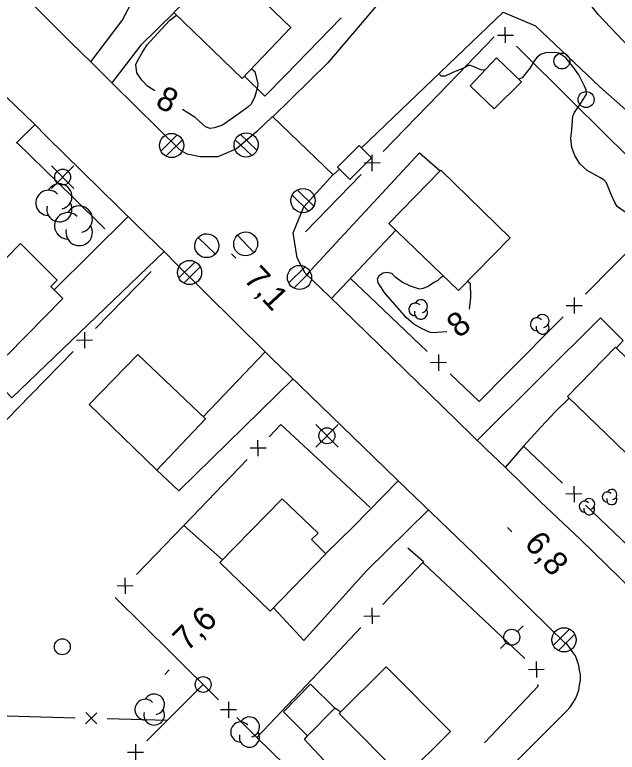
# Model space of a CAD drawing. Extents: x 381879 to 384696, y 5564785 to 5567594.
# Drawn here: x 383164.9 to 383240.4, y 5565288.9 to 5565381.4 of the extents above; entities that cross this region are included whole.
import ezdxf

# ---------------------------------------------------------------- set-up
doc = ezdxf.new("R2010")
doc.units = 0
for name, color, linetype in [('Niveau 19', 7, 'Continuous'), ('Niveau 2', 7, 'Continuous'), ('Niveau 21', 7, 'Continuous'), ('Niveau 3', 7, 'Continuous'), ('Niveau 31', 7, 'Continuous'), ('Niveau 36', 7, 'Continuous'), ('Niveau 37', 7, 'Continuous'), ('Niveau 44', 7, 'Continuous')]:
    doc.layers.add(name, color=color, linetype=linetype)

msp = doc.modelspace()

# ---------------------------------------------------------------- linework, layer by layer
at = {"layer": 'Niveau 19'}
for points in [[(383174.4, 5565375.49), (383178.35, 5565380.67), (383181.39, 5565386.48), (383186.67, 5565392.25), (383190.82, 5565387.81)], [(383184.84, 5565381.67), (383180.62, 5565377.54), (383177.05, 5565372.85)], [(383165.13, 5565365.37), (383167.39, 5565367.61)], [(383201.48, 5565348.82), (383215.62, 5565364.08), (383218.22, 5565361.81)], [(383179.07, 5565356.11), (383169.82, 5565346.88)], [(383212.64, 5565354.39), (383204.57, 5565345.83)], [(383163.77, 5565338.83), (383161.59, 5565336.42), (383164.5, 5565333.35), (383183.6, 5565351.69)], [(383240.3, 5565339.6), (383241.18, 5565340.54), (383238.33, 5565343.4), (383222.87, 5565328)], [(383196.27, 5565339.13), (383188.51, 5565330.97)], [(383182.7, 5565324.3), (383185.44, 5565321.7), (383199.77, 5565335.74)], [(383232.63, 5565331.58), (383234.39, 5565333.32)], [(383228.67, 5565327.31), (383226.37, 5565324.63)], [(383203.86, 5565313.84), (383207.34, 5565317.2), (383212.96, 5565322.94)], [(383216.77, 5565319.3), (383208.96, 5565311.64), (383201.14, 5565302.91), (383197.3, 5565307.01)], [(383205.75, 5565293.94), (383205.01, 5565294.41)], [(383215.47, 5565275.27), (383201.2, 5565290.52), (383201.6, 5565290.97)]]:
    msp.add_lwpolyline(points, dxfattribs=at)
at = {"layer": 'Niveau 2'}
for points in [[(383182.45, 5565371.87), (383181.53, 5565372.43), (383180.79, 5565373.18), (383180.19, 5565374.12), (383180.06, 5565375.16), (383180.28, 5565375.64), (383180.87, 5565376.71), (383181.48, 5565377.62), (383182.3, 5565378.56), (383184.27, 5565380.68), (383185.16, 5565381.36)], [(383242.14, 5565356.12), (383240.41, 5565357.36), (383240.12, 5565357.84), (383239.67, 5565358.87), (383239.1, 5565360.31), (383238.74, 5565360.69), (383238.25, 5565360.98), (383236.64, 5565361.88), (383235.74, 5565362.69), (383235.09, 5565363.73), (383234.72, 5565364.77), (383234.62, 5565365.87), (383234.73, 5565366.98), (383234.84, 5565368.67), (383235.07, 5565369.13), (383235.94, 5565370.44), (383236.56, 5565371.42), (383236.51, 5565371.97), (383236.33, 5565372.46), (383235.63, 5565373.86), (383235, 5565374.76), (383233.96, 5565376.01), (383233.12, 5565376.57), (383232.57, 5565376.66), (383231.45, 5565376.62), (383230.88, 5565376.45), (383230.4, 5565376.09), (383230.06, 5565375.65)], [(383230.06, 5565375.65), (383229.5, 5565374.74), (383228.5, 5565373.49), (383228.07, 5565373.32)], [(383194.57, 5565374.63), (383194.97, 5565374.28)], [(383223.82, 5565374.43), (383223.32, 5565374.49), (383222.36, 5565374.91), (383221.87, 5565375.06), (383221.22, 5565374.75), (383219.82, 5565374.17), (383218.86, 5565373.68), (383218.32, 5565373.68), (383218.12, 5565374.05)], [(383194.97, 5565374.28), (383195.34, 5565372.68), (383195.26, 5565372.18), (383194.97, 5565371.16), (383194.51, 5565370.17), (383194.09, 5565369.81), (383192.72, 5565368.79), (383190.9, 5565367.56), (383189.9, 5565367.2), (383189.38, 5565367.15), (383188.8, 5565367.34), (383188.31, 5565367.75), (383187.51, 5565368.53), (383185.91, 5565369.5)], [(383219.06, 5565341.64), (383217.21, 5565341.5), (383216.97, 5565341.53), (383215.95, 5565342), (383214.91, 5565342.59), (383213.94, 5565343.44), (383213.17, 5565344.34), (383211.33, 5565346.44), (383210.45, 5565347.76), (383210.38, 5565348.27), (383210.63, 5565348.74), (383211.07, 5565349.02), (383211.57, 5565349.12), (383212.12, 5565348.98), (383212.54, 5565348.58), (383213.48, 5565347.88), (383214.46, 5565347.4), (383215.59, 5565347.03), (383216.13, 5565347.12), (383216.61, 5565347.3), (383217.48, 5565347.87), (383217.95, 5565348.1), (383218.36, 5565348.49), (383218.59, 5565348.64)], [(383221.68, 5565348), (383221.99, 5565347.72)], [(383221.99, 5565347.72), (383222.04, 5565345.95), (383221.84, 5565344.46)]]:
    msp.add_lwpolyline(points, dxfattribs=at)
at = {"layer": 'Niveau 21'}
for points in [[(383238.06, 5565416.31), (383235.15, 5565406.99), (383223.7, 5565395.12), (383210.55, 5565382.93), (383204.15, 5565375.38), (383197.24, 5565368.6)], [(383287.03, 5565366.47), (383272.7, 5565366.43), (383260.45, 5565365.37), (383253.79, 5565365.29), (383248.29, 5565370.63), (383238.04, 5565381.44), (383233.93, 5565386.75), (383234.49, 5565390.02), (383241.22, 5565399.26), (383243.8, 5565407.14), (383243.07, 5565412.42), (383243.64, 5565416.32)], [(383160.7, 5565389.1), (383171.8, 5565378)], [(383208.37, 5565364.72), (383226.14, 5565381.73), (383230.19, 5565380.03), (383238.26, 5565372.36), (383249.41, 5565362.48), (383256.66, 5565360.44), (383266.73, 5565360.61), (383280.92, 5565361.12), (383288.21, 5565361.47)], [(383171.8, 5565378), (383174.6, 5565375.3)], [(383174.6, 5565375.3), (383177.2, 5565372.7)], [(383177.2, 5565372.7), (383185.6, 5565364.4)], [(383167.3, 5565367.7), (383163.8, 5565371.1)], [(383197.21, 5565368.63), (383195.18, 5565366.73), (383192.68, 5565364.58), (383190.34, 5565363.58), (383188.1, 5565363.58), (383186.49, 5565363.91), (383185.6, 5565364.4)], [(383197.21, 5565368.63), (383204.82, 5565361.32)], [(383180.1, 5565355.1), (383168.9, 5565366.1), (383167.3, 5565367.7)], [(383201.3, 5565349), (383200.3, 5565350.9), (383199.8, 5565354.03), (383201.12, 5565357.3), (383204.79, 5565361.35)], [(383204.82, 5565361.32), (383205.59, 5565362.05)], [(383183.8, 5565351.5), (383180.1, 5565355.1)], [(383196.4, 5565339), (383185, 5565350.3), (383183.8, 5565351.5)], [(383201.3, 5565349), (383204.3, 5565346.1)], [(383204.3, 5565346.1), (383218.6, 5565332.2), (383224, 5565326.9)], [(383199.3, 5565336.2), (383197.1, 5565338.3), (383196.4, 5565339)], [(383212.9, 5565323), (383209.9, 5565325.9), (383199.3, 5565336.2)], [(383224, 5565326.9), (383225.5, 5565325.5), (383226.4, 5565324.6)], [(383226.4, 5565324.6), (383230.8, 5565320.3)], [(383234, 5565302.5), (383222.5, 5565313.8), (383212.9, 5565323)], [(383242.4, 5565309.2), (383235.8, 5565315.6), (383230.8, 5565320.3)], [(383234.1, 5565294.1), (383234.5, 5565294.5), (383234.8, 5565295), (383235.2, 5565295.6), (383235.4, 5565296.1), (383235.6, 5565296.7), (383235.7, 5565297.3), (383235.8, 5565298), (383235.8, 5565298.6), (383235.7, 5565299.2), (383235.6, 5565299.8), (383235.4, 5565300.4), (383235.2, 5565301), (383234.8, 5565301.5), (383234.5, 5565302), (383234.1, 5565302.5), (383234, 5565302.5)], [(383219.3, 5565279.2), (383221.3, 5565281.3), (383234.1, 5565294.1)]]:
    msp.add_lwpolyline(points, dxfattribs=at)
at = {"layer": 'Niveau 3'}
for p, q in [((383192.04, 5565351.42), (383192.61, 5565350.85)), ((383226.65, 5565317.08), (383227.22, 5565316.53)), ((383183.68, 5565298.67), (383184.25, 5565299.24))]:
    msp.add_line(p, q, dxfattribs=at)
at = {"layer": 'Niveau 31'}
for points in [[(383193.4, 5565373.4), (383199.5, 5565379.8), (383191, 5565388), (383184.8, 5565381.7)], [(383228.4, 5565373), (383225.3, 5565376), (383222, 5565372.5), (383225, 5565369.6)], [(383209.62, 5565363.46), (383206.88, 5565360.75), (383205.34, 5565362.3), (383208.08, 5565365.01)], [(383220.5, 5565346.8), (383227, 5565353.4), (383218.3, 5565361.9), (383211.8, 5565355.2)], [(383163.9, 5565338.7), (383170.9, 5565345.8), (383169.4, 5565347.3), (383170.2, 5565348.1), (383165.6, 5565352.7), (383157.8, 5565344.8)], [(383234.2, 5565333.5), (383240.2, 5565339.7), (383248.8, 5565331.4), (383242.8, 5565325.2)], [(383182.7, 5565324.3), (383188.8, 5565330.7), (383180.3, 5565338.8), (383174.2, 5565332.5)], [(383198.4, 5565320.7), (383202.9, 5565316.4), (383202.1, 5565315.6), (383203.9, 5565313.8), (383196.9, 5565306.6), (383190.6, 5565312.7)], [(383211.46, 5565299.61), (383219.5, 5565291.51), (383213.61, 5565285.67), (383205.57, 5565293.77)], [(383205.01, 5565294.41), (383201.6, 5565290.97), (383198.56, 5565293.98), (383201.97, 5565297.42)]]:
    msp.add_lwpolyline(points, close=True, dxfattribs=at)
at = {"layer": 'Niveau 36'}
for p, q in [((383185.23, 5565366.34), (383183.17, 5565364.3)), ((383195.24, 5565364.43), (383193.14, 5565366.42)), ((383183.83, 5565363.66), (383185.89, 5565365.7)), ((383192.52, 5565365.73), (383194.62, 5565363.74)), ((383172.29, 5565362.44), (383169.47, 5565359.62)), ((383172.29, 5565359.62), (383169.47, 5565362.44)), ((383199.66, 5565358.76), (383201.73, 5565356.73)), ((383202.36, 5565357.4), (383200.29, 5565359.43)), ((383190.03, 5565351.39), (383187.87, 5565353.47)), ((383194.87, 5565351.58), (383192.79, 5565353.74)), ((383187.48, 5565350.41), (383185.42, 5565348.37)), ((383186.08, 5565347.73), (383188.14, 5565349.77)), ((383201.27, 5565349.79), (383199.21, 5565347.75)), ((383199.87, 5565347.11), (383201.93, 5565349.15)), ((383205.43, 5565330), (383202.61, 5565327.18)), ((383205.43, 5565327.18), (383202.61, 5565330)), ((383228.62, 5565304.74), (383227.91, 5565304.04)), ((383234.44, 5565304.34), (383232.38, 5565302.3)), ((383233.04, 5565301.66), (383235.1, 5565303.7)), ((383225.8, 5565301.91), (383226.49, 5565302.63))]:
    msp.add_line(p, q, dxfattribs=at)
for centre, radius in [((383233.493, 5565375.6), 1), ((383236.523, 5565370.76), 1), ((383184.538, 5565365.002), 1.518), ((383170.872, 5565361.035), 1), ((383186.788, 5565349.072), 1.518), ((383200.578, 5565348.452), 1.518), ((383204.012, 5565328.595), 1), ((383227.197, 5565303.325), 1), ((383233.748, 5565303.002), 1.518), ((383170.833, 5565302.13), 1), ((383188.493, 5565297.4), 1)]:
    msp.add_circle(centre, radius, dxfattribs=at)
for centre, major_axis, ratio in [((383193.882, 5565365.072), (0.024, 1.517), 0.999984), ((383201.008, 5565358.088), (-0.017, -1.517), 0.999984), ((383188.942, 5565352.434), (0.016, 1.5), 0.999983), ((383193.823, 5565352.665), (0.015, 1.5), 0.999983)]:
    msp.add_ellipse(centre, major_axis=major_axis, ratio=ratio, dxfattribs=at)
at = {"layer": 'Niveau 37'}
for p, q in [((383226.4, 5565377.86), (383226.39, 5565379.86)), ((383225.39, 5565378.86), (383227.4, 5565378.86)), ((383209.71, 5565361.8), (383209.68, 5565363.81)), ((383210.7, 5565362.82), (383208.69, 5565362.79)), ((383235.04, 5565345.94), (383235.04, 5565343.94)), ((383234.04, 5565344.94), (383236.04, 5565344.95)), ((383173.6, 5565341.6), (383173.62, 5565339.6)), ((383172.61, 5565340.59), (383174.61, 5565340.61)), ((383217.99, 5565338.77), (383218.03, 5565336.76)), ((383219.01, 5565337.79), (383217.01, 5565337.74)), ((383195.4, 5565326.04), (383195.37, 5565328.04)), ((383196.39, 5565327.06), (383194.38, 5565327.02)), ((383234.98, 5565322.28), (383235.03, 5565320.28)), ((383236, 5565321.3), (383234, 5565321.25)), ((383178.75, 5565308.75), (383178.71, 5565310.76)), ((383179.73, 5565309.77), (383177.73, 5565309.74)), ((383209.64, 5565307), (383209.69, 5565305)), ((383208.66, 5565305.97), (383210.67, 5565306.02)), ((383230.25, 5565300.27), (383230.31, 5565298.26)), ((383231.28, 5565299.29), (383229.28, 5565299.24)), ((383191.68, 5565295.22), (383191.69, 5565293.22)), ((383173.73, 5565292.48), (383175.18, 5565293.86)), ((383175.14, 5565292.45), (383173.77, 5565293.9)), ((383192.68, 5565294.23), (383190.68, 5565294.21)), ((383180, 5565289.92), (383180, 5565287.92)), ((383179, 5565288.92), (383181, 5565288.92))]:
    msp.add_line(p, q, dxfattribs=at)
for points in [[(383205.79, 5565381.01), (383198.81, 5565373.84)], [(383218.04, 5565371.43), (383224.99, 5565378.61)], [(383227.81, 5565377.45), (383234.91, 5565370.41)], [(383198.81, 5565373.84), (383196.22, 5565371.17), (383193.7, 5565373.71)], [(383211.08, 5565364.24), (383218.04, 5565371.43)], [(383234.91, 5565370.41), (383242.01, 5565363.36)], [(383165.05, 5565365.28), (383165.13, 5565365.37), (383172.19, 5565358.46)], [(383201.35, 5565354.18), (383208.3, 5565361.37)], [(383172.19, 5565358.46), (383176.16, 5565354.57)], [(383243.49, 5565353.46), (383236.45, 5565346.36)], [(383181.99, 5565349.19), (383175.01, 5565342.03)], [(383209.34, 5565346.06), (383206.94, 5565348.35)], [(383216.57, 5565339.15), (383209.34, 5565346.06)], [(383233.63, 5565343.52), (383226.59, 5565336.42)], [(383172.21, 5565339.17), (383165.23, 5565332.01)], [(383226.59, 5565336.42), (383223.1, 5565332.9), (383219.46, 5565336.38)], [(383165.23, 5565332.01), (383159.79, 5565326.43), (383158.2, 5565327.96)], [(383230.88, 5565329.7), (383232.63, 5565331.58)], [(383196.77, 5565328.48), (383198.25, 5565330.01), (383204.01, 5565324.65)], [(383233.55, 5565322.66), (383228.67, 5565327.31), (383230.88, 5565329.7)], [(383187.06, 5565318.4), (383194, 5565325.6)], [(383204.01, 5565324.65), (383209.44, 5565319.59)], [(383243.69, 5565313), (383236.45, 5565319.9)], [(383180.12, 5565311.2), (383186.06, 5565317.36), (383187.06, 5565318.4)], [(383186.06, 5565317.36), (383190.92, 5565313.02)], [(383214.18, 5565314.54), (383216.13, 5565312.82), (383216.03, 5565312.72), (383211.04, 5565307.45)], [(383221.55, 5565307.5), (383216.23, 5565312.53), (383216.23, 5565312.54), (383216.03, 5565312.72)], [(383184.55, 5565301.29), (383177.44, 5565308.32)], [(383228.82, 5565300.64), (383221.55, 5565307.5)], [(383208.29, 5565304.54), (383201.41, 5565297.28)], [(383190.43, 5565295.49), (383184.55, 5565301.29)], [(383188.48, 5565297.41), (383181.41, 5565290.34)], [(383201.41, 5565297.28), (383195.23, 5565290.75), (383192.73, 5565293.25)], [(383223.77, 5565290.09), (383230.52, 5565297.2), (383230.53, 5565297.4)], [(383162.46, 5565293.5), (383172.46, 5565293.23)], [(383176.46, 5565293.12), (383183.98, 5565292.91)], [(383195.23, 5565290.75), (383202.37, 5565283.75)]]:
    msp.add_lwpolyline(points, dxfattribs=at)
at = {"layer": 'Niveau 44'}
for centre, radius, start, end in [((383170.459, 5565358.6), 1.586, 282.26915, 149.72624), ((383169.095, 5565357.807), 1.586, 44.11535, 269.80394), ((383170.459, 5565357.014), 1.586, 166.93684, 29.62121), ((383172.946, 5565355.76), 1.66, 282.26915, 149.72624), ((383171.519, 5565354.93), 1.66, 44.11535, 269.80394), ((383172.946, 5565354.1), 1.66, 166.93684, 29.62121), ((383215.81, 5565344.842), 0.815, 282.26915, 149.72624), ((383215.109, 5565344.434), 0.815, 44.11535, 269.80394), ((383215.81, 5565344.027), 0.815, 166.93684, 29.62121), ((383231.061, 5565342.985), 0.821, 282.26915, 149.72624), ((383230.355, 5565342.575), 0.821, 44.11535, 269.80394), ((383231.061, 5565342.164), 0.821, 166.93684, 29.62121), ((383239.739, 5565321.227), 0.64, 282.26915, 149.72624), ((383236.918, 5565320.049), 0.681, 282.26915, 149.72624), ((383239.188, 5565320.907), 0.64, 44.11535, 269.80394), ((383239.739, 5565320.587), 0.64, 166.93684, 29.62121), ((383236.333, 5565319.709), 0.681, 44.11535, 269.80394), ((383236.918, 5565319.368), 0.681, 166.93684, 29.62121), ((383182.342, 5565294.903), 1.298, 282.26915, 149.72624), ((383181.226, 5565294.255), 1.298, 44.11535, 269.80394), ((383182.342, 5565293.606), 1.298, 166.93684, 29.62121), ((383194.294, 5565292.065), 1.264, 282.26915, 149.72624), ((383193.207, 5565291.433), 1.264, 44.11535, 269.80394), ((383194.294, 5565290.801), 1.264, 166.93684, 29.62121)]:
    msp.add_arc(centre, radius, start, end, dxfattribs=at)

# ---------------------------------------------------------------- texts
at = {"layer": 'Niveau 2'}
for rotation, p in [(332.17861, (383182.34, 5565369.99)), (38.48681, (383220.56, 5565340.75))]:
    msp.add_text('8', height=3, rotation=rotation, dxfattribs=at).set_placement(p)
at = {"layer": 'Niveau 3'}
for s, height, rotation, p in [('7,1  ', 3, 312.84506, (383193.45, 5565348.17)), ('6,8  ', 2.9996, 310.86178, (383228.65, 5565315.01)), ('7,6', 3, 44.7717, (383186.49, 5565301.43))]:
    msp.add_text(s, height=height, rotation=rotation, dxfattribs=at).set_placement(p)

doc.saveas('drawing.dxf')
